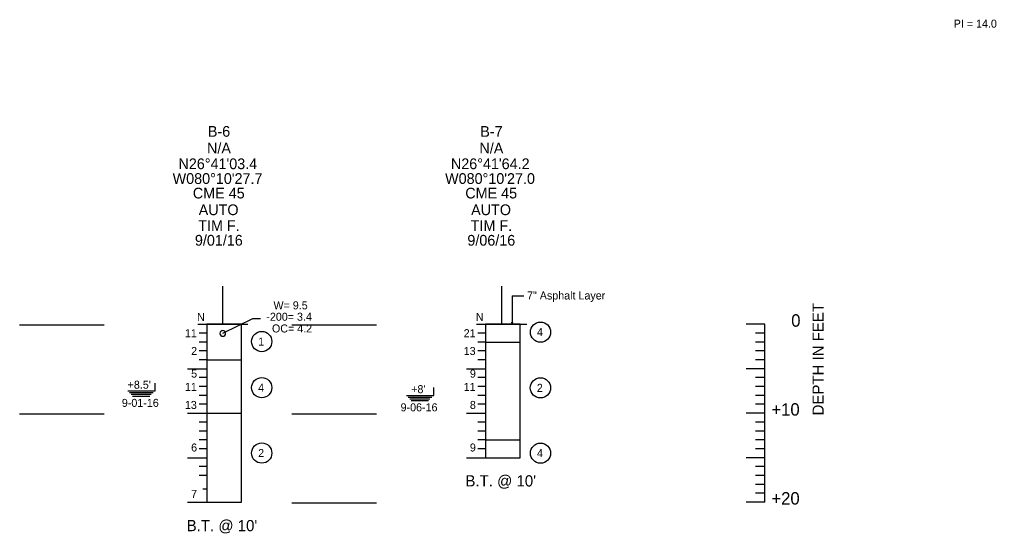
# Model space of a CAD drawing. Extents: x 0 to 331, y -72 to 117.
# Drawn here: x 31.61 to 61.03, y 7.05 to 22.53 of the extents above; entities that cross this region are included whole.
import ezdxf

# ---------------------------------------------------------------- set-up
doc = ezdxf.new("R2010")
doc.units = 0
for name, color, linetype in [('1-BORE', 7, 'Continuous'), ('1-GRID', 7, 'Continuous'), ('1-TEXT', 7, 'Continuous')]:
    doc.layers.add(name, color=color, linetype=linetype)

msp = doc.modelspace()

# ---------------------------------------------------------------- linework, layer by layer
at = {"layer": '1-BORE'}
for p, q in [((46.444, 14.214), (46.795, 14.214)), ((37.73, 13.083), (38.634, 13.523)), ((38.634, 13.523), (38.862, 13.523)), ((46.444, 13.352), (46.431, 13.419)), ((46.444, 13.388), (46.431, 13.419)), ((46.444, 13.352), (46.458, 13.419)), ((46.444, 13.388), (46.458, 13.419)), ((46.444, 13.352), (46.444, 13.388)), ((46.444, 13.352), (46.444, 13.388)), ((45.638, 12.816), (46.683, 12.816)), ((37.243, 12.281), (38.288, 12.281)), ((37.243, 10.673), (38.288, 10.673)), ((45.638, 9.869), (46.683, 9.869)), ((45.638, 9.333), (46.683, 9.333)), ((37.128, 8.396), (37.243, 8.396)), ((37.243, 7.994), (38.288, 7.994))]:
    msp.add_line(p, q, dxfattribs=at)
for points in [[(38.288, 7.994), (38.288, 13.352), (37.243, 13.352), (37.243, 7.994)], [(46.683, 9.333), (46.683, 13.352), (45.638, 13.352), (45.638, 9.333)]]:
    msp.add_lwpolyline(points, dxfattribs=at)
for start, end in [(0, 180), (180, 0)]:
    msp.add_arc((37.728, 13.077), 0.0848, start, end, dxfattribs=at)
at = {"layer": '1-GRID'}
for p, q in [((31.608, 13.334), (34.161, 13.334)), ((39.807, 13.334), (42.361, 13.334)), ((54.051, 13.352), (53.487, 13.352)), ((54.051, 13.084), (53.766, 13.084)), ((54.051, 12.816), (53.766, 12.816)), ((54.051, 12.548), (53.766, 12.548)), ((54.051, 12.281), (53.766, 12.281)), ((54.051, 12.013), (53.487, 12.013)), ((54.051, 12.013), (53.487, 12.013)), ((54.051, 11.745), (53.766, 11.745)), ((54.051, 11.477), (53.766, 11.477)), ((54.051, 11.209), (53.766, 11.209)), ((54.051, 10.941), (53.766, 10.941)), ((31.608, 10.655), (34.161, 10.655)), ((39.807, 10.655), (42.361, 10.655)), ((54.051, 10.673), (53.487, 10.673)), ((54.051, 10.405), (53.766, 10.405)), ((54.051, 10.137), (53.766, 10.137)), ((54.051, 9.869), (53.766, 9.869)), ((54.051, 9.601), (53.766, 9.601)), ((54.051, 9.333), (53.487, 9.333)), ((54.051, 9.333), (53.487, 9.333)), ((54.051, 9.065), (53.766, 9.065)), ((54.051, 8.797), (53.766, 8.797)), ((54.051, 8.529), (53.766, 8.529)), ((54.051, 8.262), (53.766, 8.262)), ((39.807, 7.975), (42.361, 7.975)), ((54.051, 7.994), (53.487, 7.994))]:
    msp.add_line(p, q, dxfattribs=at)
for points in [[(54.051, 10.673), (54.051, 13.352)], [(54.051, 7.994), (54.051, 10.673)]]:
    msp.add_lwpolyline(points, dxfattribs=at)
at = {"layer": '1-TEXT'}
for p, q in [((37.723, 14.503), (37.723, 13.352)), ((46.118, 14.503), (46.118, 13.352)), ((46.444, 14.214), (46.444, 13.352)), ((37.243, 13.084), (37.013, 13.084)), ((45.638, 13.084), (45.409, 13.084)), ((37.243, 12.816), (37.013, 12.816)), ((45.638, 12.816), (45.409, 12.816)), ((37.243, 12.548), (37.013, 12.548)), ((45.638, 12.548), (45.409, 12.548)), ((37.243, 12.281), (37.013, 12.281)), ((45.638, 12.281), (45.409, 12.281)), ((36.67, 12.013), (37.243, 12.013)), ((45.065, 12.013), (45.638, 12.013)), ((35.691, 11.343), (35.691, 11.579)), ((37.243, 11.745), (37.013, 11.745)), ((37.243, 11.477), (37.013, 11.477)), ((45.638, 11.745), (45.409, 11.745)), ((45.638, 11.477), (45.409, 11.477)), ((34.865, 11.343), (35.691, 11.343)), ((34.92, 11.294), (35.629, 11.294)), ((34.967, 11.245), (35.573, 11.245)), ((35.006, 11.186), (35.53, 11.186)), ((37.243, 11.209), (37.013, 11.209)), ((43.259, 11.209), (44.085, 11.209)), ((44.085, 11.209), (44.085, 11.445)), ((45.638, 11.209), (45.409, 11.209)), ((37.243, 10.941), (37.013, 10.941)), ((43.314, 11.16), (44.024, 11.16)), ((43.361, 11.111), (43.968, 11.111)), ((43.4, 11.052), (43.924, 11.052)), ((45.638, 10.941), (45.409, 10.941)), ((36.67, 10.673), (37.243, 10.673)), ((45.065, 10.673), (45.638, 10.673)), ((37.243, 10.405), (37.013, 10.405)), ((45.638, 10.405), (45.409, 10.405)), ((37.243, 10.137), (37.013, 10.137)), ((45.638, 10.137), (45.409, 10.137)), ((37.243, 9.869), (37.013, 9.869)), ((45.638, 9.869), (45.409, 9.869)), ((37.243, 9.601), (37.013, 9.601)), ((45.638, 9.601), (45.409, 9.601)), ((36.67, 9.333), (37.243, 9.333)), ((45.065, 9.333), (45.638, 9.333)), ((37.243, 9.065), (37.013, 9.065)), ((37.243, 8.797), (37.013, 8.797)), ((36.67, 7.994), (37.243, 7.994))]:
    msp.add_line(p, q, dxfattribs=at)
for points in [[(36.976, 13.352), (38.485, 13.352)], [(45.372, 13.352), (46.881, 13.352)]]:
    msp.add_lwpolyline(points, dxfattribs=at)
for centre in [(47.297, 13.116), (38.901, 12.832), (38.901, 11.443), (47.294, 11.437), (38.901, 9.473), (47.297, 9.47)]:
    msp.add_circle(centre, 0.305, dxfattribs=at)

# ---------------------------------------------------------------- texts
at = {"layer": '1-GRID'}
msp.add_text('DEPTH IN FEET', height=0.3376, rotation=90, dxfattribs=at).set_placement((55.825, 10.607))
for s, height, p in [('0', 0.375, (54.847, 13.279)), ('+10', 0.3751, (54.25, 10.6)), ('+20', 0.3751, (54.25, 7.921))]:
    msp.add_text(s, height=height, dxfattribs=at).set_placement(p)
at = {"layer": '1-TEXT'}
for s, height, p in [('PI = 14.0', 0.2411, (59.74, 22.288)), ('B-6', 0.3231, (37.279, 19.002)), ('B-7', 0.3231, (45.483, 19)), ('N/A', 0.3231, (37.254, 18.497)), ('N/A', 0.3231, (45.458, 18.497)), ("N26°41'03.4", 0.32313, (36.394, 18.025)), ("N26°41'64.2", 0.32313, (44.598, 18.025)), ("W080°10'27.7", 0.32313, (36.218, 17.581)), ("W080°10'27.0", 0.32313, (44.423, 17.581)), ('CME 45', 0.3231, (36.827, 17.142)), ('CME 45', 0.3231, (45.031, 17.142)), ('AUTO', 0.3231, (37.003, 16.64)), ('AUTO', 0.3231, (45.207, 16.64)), ('TIM F.', 0.3231, (36.99, 16.165)), ('TIM F.', 0.3231, (45.195, 16.165)), ('9/01/16', 0.3231, (36.889, 15.721)), ('9/06/16', 0.3231, (45.094, 15.721)), ('7" Asphalt Layer', 0.24114, (46.891, 14.099)), ('W= 9.5', 0.2411, (39.255, 13.802)), ('N', 0.241, (36.952, 13.455)), ('-200= 3.4', 0.2411, (39.04, 13.459)), ('N', 0.241, (45.347, 13.455)), ('OC= 4.2', 0.2411, (39.209, 13.106)), ('11', 0.2411, (36.587, 12.963)), ('1', 0.241, (38.794, 12.713)), ('21', 0.2411, (44.983, 12.963)), ('4', 0.241, (47.189, 12.996)), ('2', 0.241, (36.775, 12.427)), ('13', 0.2411, (44.983, 12.427)), ('5', 0.241, (36.775, 11.746)), ('9', 0.241, (45.17, 11.746)), ("+8.5'", 0.2411, (34.863, 11.411)), ('11', 0.2411, (36.587, 11.347)), ('4', 0.241, (38.794, 11.323)), ("+8'", 0.2411, (43.402, 11.277)), ('11', 0.2411, (44.983, 11.347)), ('2', 0.241, (47.187, 11.317)), ('9-01-16', 0.2411, (34.689, 10.864)), ('13', 0.2411, (36.587, 10.802)), ('9-06-16', 0.2411, (43.083, 10.73)), ('8', 0.241, (45.17, 10.802)), ('6', 0.241, (36.775, 9.52)), ('9', 0.241, (45.17, 9.52)), ('2', 0.241, (38.794, 9.354)), ('4', 0.241, (47.189, 9.35)), ("B.T. @ 10'", 0.3376, (45.036, 8.467)), ('7', 0.241, (36.775, 8.123)), ("B.T. @ 10'", 0.3376, (36.641, 7.119))]:
    msp.add_text(s, height=height, dxfattribs=at).set_placement(p)

doc.saveas('drawing.dxf')
